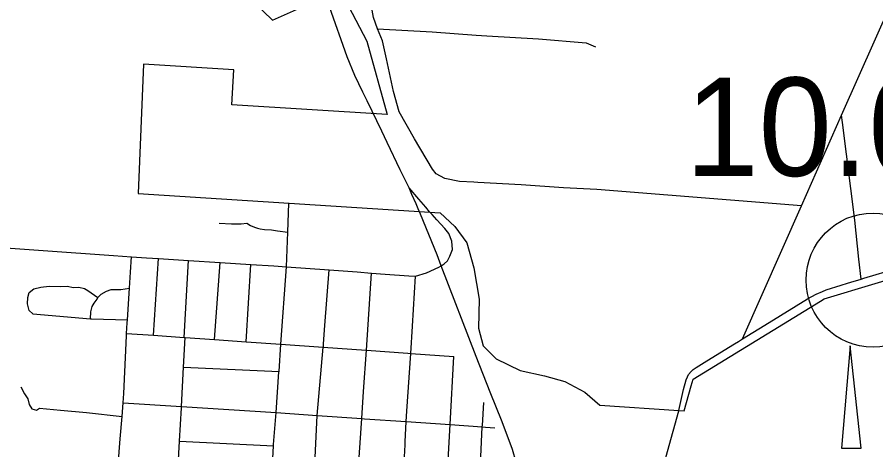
# Model space of a CAD drawing. Extents: x 1729596 to 1934326, y 644115 to 911751.
# Drawn here: x 1805996 to 1815592, y 840922 to 845758 of the extents above; entities that cross this region are included whole.
import ezdxf

# ---------------------------------------------------------------- set-up
doc = ezdxf.new("R2010")
doc.units = 0
for name, color, linetype in [('Default', 7, 'Continuous'), ('GM_X_City_Street', 7, 'Continuous'), ('GM_X_Corporation', 7, 'Continuous'), ('GM_X_County_Road', 7, 'Continuous'), ('GM_X_Township_Road', 7, 'Continuous'), ('GM_X_US_Route', 7, 'Continuous')]:
    doc.layers.add(name, color=color, linetype=linetype)

msp = doc.modelspace()

# ---------------------------------------------------------------- linework, layer by layer
at = {"layer": 'Default'}
msp.add_circle((1815561.9, 842818.8), 750, dxfattribs=at)
at = {"layer": 'GM_X_City_Street'}
for points in [[(1809004, 842969.2), (1809019, 843354.8), (1809031.6, 843678.8)], [(1810632.4, 843552.5), (1810604.7, 843582.4), (1810562.5, 843634), (1810486.3, 843722.2)], [(1810447.9, 842861.2), (1810569.8, 842898.6), (1810708.7, 842962.7), (1810736, 842980.4), (1810768.8, 843001.8), (1810805.7, 843035), (1810832.8, 843084.8), (1810853.9, 843142.8), (1810859.1, 843162.2), (1810854.1, 843253.1), (1810818.4, 843338.6), (1810774.9, 843396.8), (1810686.7, 843493.6), (1810632.4, 843552.5)], [(1808253.4, 843457.2), (1808389.3, 843449.7), (1808457.3, 843449), (1808499.3, 843448.5), (1808561.4, 843455.9), (1808603.1, 843429.4), (1808646.9, 843408.9), (1808682.9, 843400.5), (1808712.8, 843392.1), (1808760.7, 843383.6), (1808836.7, 843380.8), (1808904.6, 843370.1), (1809019, 843354.8)], [(1803987, 843293.2), (1804403.2, 843272.9), (1804883.6, 843249.4), (1804964.4, 843245.2), (1805442.8, 843210.6), (1807071.2, 843092.5), (1807273.6, 843079.2)], [(1807226.5, 842342.8), (1807228.4, 842373.4), (1807251.2, 842730.5), (1807262.5, 842906.9), (1807273.6, 843079.2)], [(1807273.6, 843079.2), (1807439.8, 843067.3), (1807573.3, 843058.9), (1807909.4, 843037.9), (1808262.9, 843015.8), (1808608.7, 842994.1), (1808862.6, 842978.3), (1809004, 842969.2)], [(1807520.7, 842202.2), (1807573.3, 843058.9)], [(1807860.5, 842178.2), (1807909.4, 843037.9)], [(1808200.3, 842154.3), (1808262.9, 843015.8)], [(1808556.3, 842129.2), (1808608.7, 842994.1)], [(1808722.6, 838892.2), (1808741.1, 839209.8), (1808771.6, 839585.9), (1808772.5, 839597), (1808808.5, 840062), (1808828.6, 840321.3), (1808861.4, 840964.8), (1808862.2, 840980.1), (1808888.3, 841337.4), (1808921.7, 841794.1), (1808922, 841798), (1808943.3, 842102), (1809004, 842969.2)], [(1809004, 842969.2), (1809482.8, 842933.5), (1809793.9, 842910.2), (1809955.8, 842898.1), (1810109.8, 842886.6), (1810373.1, 842866.9), (1810447.9, 842861.2)], [(1809435.3, 842312.4), (1809435.3, 842312.5), (1809482.8, 842933.5)], [(1809597.8, 837843), (1809635.6, 838286.6), (1809679.1, 838821.8), (1809692, 839043.9), (1809725.7, 839516.3), (1809777.3, 840239), (1809846.6, 841271.4), (1809866.9, 841573.3), (1809897.9, 842034.7), (1809955.8, 842898.1)], [(1810333.1, 841012.4), (1810344.7, 841237.2), (1810350.8, 841354.7), (1810394.6, 841999.8), (1810415.3, 842303.8), (1810447.9, 842861.2)], [(1806171, 842443.1), (1806131.4, 842479.6), (1806112.1, 842552), (1806114.9, 842626.1), (1806129.4, 842682.1), (1806181.8, 842719.6), (1806260, 842738.8), (1806354.1, 842749.8), (1806480.1, 842748.5), (1806554.2, 842751.7), (1806624, 842734.9), (1806684.1, 842740.3), (1806747.9, 842725.6), (1806785.7, 842703.1), (1806895.5, 842626.1)], [(1806814.3, 842387), (1806817.3, 842464.2), (1806833.9, 842524.2), (1806854.3, 842560.1), (1806888.7, 842607.8), (1806895.5, 842626.1), (1806933.3, 842663.4), (1806993.6, 842694.9), (1807045.8, 842712.4), (1807111.8, 842713.6), (1807155.8, 842713.2), (1807251.2, 842730.5)], [(1806171, 842443.1), (1806814.3, 842387), (1806826.5, 842385.9), (1807228.4, 842373.4)], [(1807186.1, 841553.2), (1807217, 842194.6), (1807218.9, 842223.4), (1807226.4, 842342.3), (1807226.5, 842342.8)], [(1809419.5, 842105.4), (1809419.5, 842105.5), (1809435.3, 842312.4)], [(1807218.9, 842223.4), (1807520.7, 842202.2), (1807860.5, 842178.2), (1807874.4, 842177.3), (1808200.3, 842154.3), (1808556.3, 842129.2), (1808943.3, 842102), (1809416.6, 842068.7), (1809897.6, 842034.8)], [(1807830.4, 841393.7), (1807831.1, 841405.8), (1807855.8, 841845.7), (1807874.4, 842177.3)], [(1809299.6, 840293), (1809349.8, 841305.6), (1809416.6, 842068.7), (1809417.5, 842079.6), (1809419.5, 842105.4)], [(1809897.6, 842034.8), (1809897.9, 842034.7), (1810361.2, 842002.1), (1810361.2, 842002.1)], [(1810361.2, 842002.1), (1810394.6, 841999.8), (1810876.4, 841965.8)], [(1810681.3, 838748.6), (1810712.6, 839210.6), (1810776, 840146.7), (1810779.1, 840202.9), (1810834.3, 841203.5), (1810876.4, 841965.8)], [(1807855.8, 841845.7), (1808922, 841798)], [(1806034.8, 841626.6), (1806078, 841548), (1806113.4, 841491.5), (1806128.8, 841429.2), (1806160.3, 841380.7), (1806212.2, 841366.1), (1806246.4, 841387.8), (1806478.2, 841365.3), (1806771.9, 841338.1), (1807168, 841293.8)], [(1807100.8, 840456.4), (1807147, 841044.1), (1807168, 841293.8), (1807181.1, 841448), (1807186.1, 841553.1), (1807186.1, 841553.2)], [(1807181.1, 841448), (1807831.1, 841405.8), (1808888.3, 841337.4)], [(1811194.9, 841194.2), (1811211.1, 841449.1)], [(1807774.8, 840401.3), (1807809.4, 841018.5), (1807830.4, 841393.1), (1807830.4, 841393.7)], [(1808888.3, 841337.4), (1809349.8, 841305.6), (1809846.6, 841271.4), (1809877.1, 841269.3)], [(1809877.1, 841269.3), (1809877.1, 841269.3), (1810344.7, 841237.2), (1810834.3, 841203.5), (1811194, 841178.8), (1811230.2, 841176.3)], [(1811146.9, 840173.7), (1811194, 841178.8), (1811194.3, 841185.2), (1811194.9, 841194.2)], [(1811230.2, 841176.3), (1811230.2, 841176.3), (1811334.3, 841169.2)], [(1807809.4, 841018.5), (1808861.4, 840964.8)], [(1810209.4, 839201.5), (1810212.3, 839240.1), (1810223, 839380.3), (1810290.3, 840241.7), (1810331.4, 840978.6), (1810333.1, 841012.4)]]:
    msp.add_lwpolyline(points, dxfattribs=at)
at = {"layer": 'GM_X_Corporation'}
for points in [[(1808107.2, 846443.6), (1808850, 845723.9), (1809452.7, 845995.8)], [(1809494.6, 846276.2), (1809904.5, 845489.7), (1810130.3, 844669.2), (1808393.9, 844779.1), (1808418.5, 845169.4), (1807405.6, 845233.6), (1807346.1, 843786.9), (1810722.5, 843570.4), (1810886.9, 843419.9), (1811021.2, 843235.3), (1811097.5, 842956.5), (1811157.7, 842605.5), (1811151.7, 842280.5), (1811201.9, 842085.9), (1811350.2, 841937.5), (1811618.9, 841807), (1811889.6, 841750.8), (1812116.8, 841685.4), (1812340.6, 841568.1), (1812507.1, 841419.6), (1813390.6, 841360.2), (1813448.7, 841356.3), (1813528.7, 841636.6), (1813550, 841711.4), (1814974.2, 842584.2), (1815015.7, 842609.9), (1816153.3, 842950.9)]]:
    msp.add_lwpolyline(points, dxfattribs=at)
msp.add_lwpolyline([(1815209.9, 840939.2), (1815426.9, 840939.3), (1815307.2, 842084)], close=True, dxfattribs=at)
at = {"layer": 'GM_X_County_Road'}
for points in [[(1814100.7, 842163.9), (1814760.4, 843649.3), (1815210.3, 844662.2), (1816319.7, 847160.1), (1816350.6, 847229.4), (1816426.4, 847397.7), (1816452.3, 847455.2)], [(1810486.3, 843722.2), (1810376.6, 843849.3)]]:
    msp.add_lwpolyline(points, dxfattribs=at)
at = {"layer": 'GM_X_Township_Road'}
for points in [[(1811144.9, 843911.8), (1811099, 843914.6), (1810940.5, 843920.8), (1810776, 843956.4), (1810680.1, 844008.5), (1810636.2, 844057.9), (1810436.4, 844398.8), (1810264.4, 844698.8), (1810200.4, 844927), (1810123.5, 845290.8), (1810077.9, 845491.7), (1810023.2, 845627.3), (1809977, 845754.1), (1809918.6, 846083.5), (1809777, 847203.8), (1809776.7, 847295.3)], [(1810023.2, 845627.3), (1810634.3, 845595.6), (1811124.3, 845558.1), (1811246.3, 845550.5)], [(1811246.3, 845550.5), (1811821, 845515.1), (1812355.5, 845470.8), (1812460, 845426.6)], [(1815428.8, 842830.9), (1815401.8, 843054.9), (1815358, 843488), (1815219, 844581.3), (1815210.3, 844662.2)], [(1814760.4, 843649.3), (1812472.6, 843830.3), (1812102.5, 843852.2), (1811628.4, 843882.4), (1811144.9, 843911.8)]]:
    msp.add_lwpolyline(points, dxfattribs=at)
at = {"layer": 'GM_X_US_Route'}
for points in [[(1809905.6, 844821.6), (1809858.8, 844917.9), (1809769.4, 845105.7), (1809683.8, 845316.4), (1809486.2, 845871.7)], [(1810129.9, 844358.6), (1810069.4, 844484.2), (1809905.6, 844821.6)], [(1810408.1, 843777.5), (1810376.6, 843849.3), (1810277.2, 844052.4), (1810129.9, 844358.6)], [(1810476.9, 843616.7), (1810455.4, 843669.7), (1810408.1, 843777.5)], [(1811573, 840785.7), (1811530.4, 840925.8), (1811417.8, 841233.3), (1811280.8, 841568.2), (1811125.6, 841964), (1810736, 842980.4), (1810688.9, 843103.2), (1810501.8, 843555.1), (1810476.9, 843616.7)], [(1815275.4, 842784.8), (1815312.9, 842796.1), (1815428.8, 842830.9), (1815459, 842839.4), (1815833.8, 842951.1)], [(1814013.6, 842106.5), (1814057.1, 842133.1), (1814100.7, 842163.9), (1814400.9, 842346.5), (1814829, 842608.4), (1814924.8, 842660.8), (1814995.9, 842693.2), (1815037.5, 842709.9), (1815204.6, 842763.7), (1815275.4, 842784.8)], [(1813389.6, 841356.6), (1813390.6, 841360.2), (1813442.5, 841595.8), (1813471.4, 841704.8), (1813485.6, 841738.8), (1813500, 841764), (1813527.2, 841798.2), (1813549.8, 841819.6), (1813583.2, 841843.1), (1813704.4, 841917.7), (1814013.6, 842106.5)], [(1812711, 838944.9), (1812876.8, 839516.3), (1812928.3, 839693.8), (1812983.8, 839886.5), (1813144.2, 840465.7), (1813264.3, 840904.6), (1813389.6, 841356.6)]]:
    msp.add_lwpolyline(points, dxfattribs=at)

# ---------------------------------------------------------------- texts
at = {"layer": 'Default'}
msp.add_text('10.00', height=1100, dxfattribs=at).set_placement((1813464, 843983.2))

doc.saveas('drawing.dxf')
